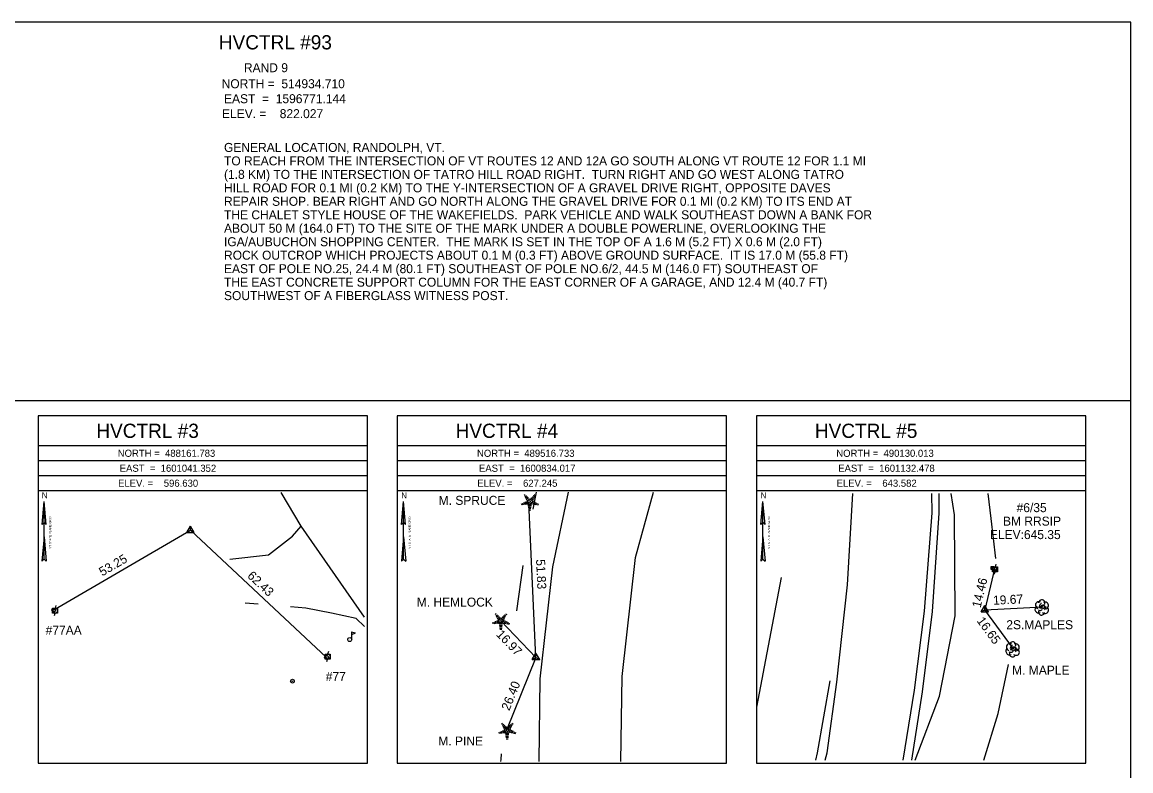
# Model space of a CAD drawing. Extents: x 1598730 to 1599370, y 501440 to 502728.
# Drawn here: x 1598999.2 to 1599369.5, y 502477.7 to 502727.8 of the extents above; entities that cross this region are included whole.
import ezdxf

# ---------------------------------------------------------------- set-up
doc = ezdxf.new("R2010")
doc.units = 0
for name, color, linetype in [('CBP', 7, 'Continuous'), ('CPBM', 7, 'Continuous'), ('CPSM', 7, 'Continuous'), ('Default', 7, 'Continuous'), ('L_C', 7, 'Continuous'), ('LARO', 7, 'Continuous'), ('LAWA', 7, 'Continuous'), ('LMB', 7, 'Continuous'), ('LTC', 7, 'Continuous'), ('LTD', 7, 'Continuous'), ('NBL1', 7, 'Continuous'), ('NBL2', 7, 'Continuous'), ('NNA_P', 7, 'Continuous'), ('PET', 7, 'Continuous'), ('RDG', 7, 'Continuous'), ('RDP', 7, 'Continuous'), ('U_C', 7, 'Continuous'), ('UP', 7, 'Continuous'), ('UPGW', 7, 'Continuous')]:
    doc.layers.add(name, color=color, linetype=linetype)

msp = doc.modelspace()

# ---------------------------------------------------------------- linework, layer by layer
at = {"layer": 'CBP'}
for centre, radius in [((1599168.51, 502567.4), 0.625), ((1599168.51, 502567.4), 0.0833), ((1599324.01, 502545.19), 0.625), ((1599324.01, 502545.19), 0.0833), ((1599009.78, 502531.49), 0.625), ((1599009.78, 502531.49), 0.0833), ((1599340.12, 502532.53), 0.625), ((1599340.12, 502532.53), 0.0833), ((1599159.14, 502527.86), 0.625), ((1599159.14, 502527.86), 0.0833), ((1599330.38, 502518.48), 0.625), ((1599100.85, 502515.65), 0.625), ((1599100.85, 502515.65), 0.0833), ((1599330.38, 502518.48), 0.0833), ((1599160.99, 502491.31), 0.625), ((1599160.99, 502491.31), 0.0833)]:
    msp.add_circle(centre, radius, dxfattribs=at)
at = {"layer": 'CPBM'}
for p, q in [((1599322.94, 502545.01), (1599322.94, 502546.01)), ((1599322.94, 502546.01), (1599323.94, 502546.01)), ((1599323.94, 502545.01), (1599322.94, 502545.01)), ((1599323.44, 502545.51), (1599323.44, 502545.51)), ((1599323.44, 502545.51), (1599323.44, 502545.51)), ((1599323.94, 502546.01), (1599323.94, 502545.01))]:
    msp.add_line(p, q, dxfattribs=at)
at = {"layer": 'CPSM'}
for p, q in [((1599054.2, 502557.37), (1599055.45, 502559.53)), ((1599054.2, 502557.37), (1599055.45, 502558.09)), ((1599054.2, 502557.37), (1599056.7, 502557.37)), ((1599056.7, 502557.37), (1599055.45, 502559.53)), ((1599055.45, 502558.09), (1599055.45, 502559.53)), ((1599055.45, 502558.09), (1599055.45, 502558.09)), ((1599055.45, 502558.09), (1599056.7, 502557.37)), ((1599319.52, 502530.82), (1599320.77, 502532.99)), ((1599319.52, 502530.82), (1599320.77, 502531.55)), ((1599319.52, 502530.82), (1599322.02, 502530.82)), ((1599322.02, 502530.82), (1599320.77, 502532.99)), ((1599320.77, 502531.55), (1599320.77, 502532.99)), ((1599320.77, 502531.55), (1599320.77, 502531.55)), ((1599320.77, 502531.55), (1599322.02, 502530.82)), ((1599169.6, 502514.94), (1599170.85, 502517.1)), ((1599169.6, 502514.94), (1599170.85, 502515.66)), ((1599172.1, 502514.94), (1599170.85, 502517.1)), ((1599170.85, 502515.66), (1599170.85, 502517.1)), ((1599170.85, 502515.66), (1599170.85, 502515.66)), ((1599170.85, 502515.66), (1599172.1, 502514.94)), ((1599169.6, 502514.94), (1599172.1, 502514.94))]:
    msp.add_line(p, q, dxfattribs=at)
at = {"layer": 'Default'}
for p, q in [((1599170.85, 502515.66), (1599168.51, 502567.4)), ((1599009.78, 502531.49), (1599055.45, 502558.09)), ((1599055.45, 502558.09), (1599100.85, 502515.65)), ((1599324.01, 502545.19), (1599320.77, 502531.55)), ((1599320.77, 502531.55), (1599340.12, 502532.53)), ((1599330.38, 502518.48), (1599320.77, 502531.55)), ((1599159.14, 502527.86), (1599170.85, 502515.66)), ((1599170.85, 502515.66), (1599160.99, 502491.31))]:
    msp.add_line(p, q, dxfattribs=at)
at = {"layer": 'LARO'}
msp.add_lwpolyline([(1599264.34, 502481.28), (1599264.89, 502483.74), (1599269.13, 502507.78)], dxfattribs=at)
at = {"layer": 'LAWA'}
for points in [[(1599169.95, 502565.19), (1599170.97, 502570.85)], [(1599324.41, 502548.64), (1599322.86, 502561.99), (1599321.92, 502570.34)], [(1599164.4, 502531.22), (1599166.57, 502546.36)], [(1599244.67, 502499.06), (1599252.84, 502542.31)], [(1599320.42, 502481.28), (1599325.28, 502496.88), (1599328.66, 502513.24)], [(1599159.16, 502480.84), (1599159.2, 502481.48), (1599159.34, 502483.44)]]:
    msp.add_lwpolyline(points, dxfattribs=at)
at = {"layer": 'LMB'}
for p, q in [((1599109.28, 502524.2), (1599110.57, 502523.82)), ((1599109.29, 502521.61), (1599109.29, 502524.21)), ((1599109.29, 502523.3), (1599110.57, 502523.81)), ((1599108.63, 502521.6), (1599108.63, 502521.6))]:
    msp.add_line(p, q, dxfattribs=at)
msp.add_circle((1599108.63, 502521.6), 0.656, dxfattribs=at)
at = {"layer": 'LTC'}
for p, q in [((1599165.93, 502567.06), (1599166.08, 502566.59)), ((1599166.38, 502567.28), (1599166.59, 502566.63)), ((1599166.84, 502567.49), (1599167.11, 502566.66)), ((1599166.89, 502569.78), (1599167.25, 502570.04)), ((1599167.1, 502569.32), (1599167.63, 502569.7)), ((1599167.29, 502567.71), (1599167.62, 502566.69)), ((1599167.31, 502568.85), (1599168.02, 502569.36)), ((1599167.52, 502568.38), (1599168.4, 502569.02)), ((1599167.75, 502567.93), (1599168.76, 502568.66)), ((1599167.75, 502567.93), (1599168.13, 502566.74)), ((1599168.76, 502568.66), (1599169.76, 502567.94)), ((1599169.18, 502568.98), (1599169.99, 502568.39)), ((1599169.76, 502567.94), (1599169.36, 502566.74)), ((1599169.55, 502569.33), (1599170.23, 502568.83)), ((1599170.19, 502567.67), (1599169.86, 502566.63)), ((1599169.92, 502569.67), (1599170.47, 502569.27)), ((1599170.29, 502570.02), (1599170.71, 502569.72)), ((1599170.64, 502567.42), (1599170.35, 502566.53)), ((1599171.08, 502567.17), (1599170.85, 502566.44)), ((1599169.36, 502566.74), (1599168.13, 502566.74)), ((1599169.33, 502566.24), (1599168.18, 502566.24)), ((1599169.24, 502565.74), (1599168.25, 502565.74)), ((1599169.16, 502565.24), (1599168.33, 502565.24)), ((1599169.07, 502564.74), (1599168.4, 502564.74)), ((1599171.53, 502566.92), (1599171.34, 502566.34)), ((1599157.25, 502530), (1599157.6, 502530.25)), ((1599160.64, 502530.24), (1599161.06, 502529.93)), ((1599156.28, 502527.27), (1599156.43, 502526.81)), ((1599156.73, 502527.49), (1599156.95, 502526.84)), ((1599157.19, 502527.71), (1599157.46, 502526.87)), ((1599157.46, 502529.53), (1599157.98, 502529.91)), ((1599157.64, 502527.92), (1599157.98, 502526.91)), ((1599157.67, 502529.06), (1599158.37, 502529.58)), ((1599157.87, 502528.6), (1599158.75, 502529.24)), ((1599158.1, 502528.14), (1599159.11, 502528.88)), ((1599158.1, 502528.14), (1599158.49, 502526.95)), ((1599159.72, 502526.95), (1599158.49, 502526.95)), ((1599159.68, 502526.45), (1599158.53, 502526.45)), ((1599159.11, 502528.88), (1599160.11, 502528.15)), ((1599159.53, 502529.19), (1599160.34, 502528.6)), ((1599160.11, 502528.15), (1599159.72, 502526.95)), ((1599159.9, 502529.54), (1599160.58, 502529.05)), ((1599160.55, 502527.88), (1599160.21, 502526.84)), ((1599160.27, 502529.89), (1599160.82, 502529.49)), ((1599160.99, 502527.63), (1599160.7, 502526.75)), ((1599161.43, 502527.38), (1599161.2, 502526.65)), ((1599161.88, 502527.13), (1599161.69, 502526.56)), ((1599159.59, 502525.95), (1599158.61, 502525.95)), ((1599159.51, 502525.45), (1599158.68, 502525.45)), ((1599159.43, 502524.95), (1599158.75, 502524.95)), ((1599159.36, 502493.43), (1599159.72, 502493.69)), ((1599159.57, 502492.96), (1599160.1, 502493.35)), ((1599159.78, 502492.5), (1599160.49, 502493.01)), ((1599162.39, 502493.32), (1599162.94, 502492.92)), ((1599162.76, 502493.67), (1599163.18, 502493.37)), ((1599158.4, 502490.71), (1599158.55, 502490.24)), ((1599158.85, 502490.93), (1599159.06, 502490.27)), ((1599159.31, 502491.14), (1599159.58, 502490.31)), ((1599159.76, 502491.36), (1599160.09, 502490.34)), ((1599159.99, 502492.03), (1599160.87, 502492.67)), ((1599160.22, 502491.58), (1599161.23, 502492.31)), ((1599160.22, 502491.58), (1599160.6, 502490.38)), ((1599161.83, 502490.38), (1599160.6, 502490.38)), ((1599161.8, 502489.88), (1599160.65, 502489.88)), ((1599161.71, 502489.38), (1599160.72, 502489.38)), ((1599161.23, 502492.31), (1599162.22, 502491.59)), ((1599161.65, 502492.63), (1599162.46, 502492.04)), ((1599162.22, 502491.59), (1599161.83, 502490.38)), ((1599162.02, 502492.97), (1599162.7, 502492.48)), ((1599162.66, 502491.32), (1599162.32, 502490.28)), ((1599163.11, 502491.07), (1599162.82, 502490.18)), ((1599163.55, 502490.82), (1599163.31, 502490.09)), ((1599164, 502490.57), (1599163.81, 502489.99)), ((1599161.63, 502488.88), (1599160.8, 502488.88)), ((1599161.54, 502488.38), (1599160.87, 502488.38))]:
    msp.add_line(p, q, dxfattribs=at)
at = {"layer": 'LTD'}
for p, q in [((1599339.75, 502532.36), (1599339.75, 502532.36)), ((1599339.75, 502532.36), (1599339.75, 502532.36)), ((1599330.03, 502518.37), (1599330.03, 502518.37)), ((1599330.03, 502518.37), (1599330.03, 502518.37))]:
    msp.add_line(p, q, dxfattribs=at)
for centre in [(1599339.8, 502533.79), (1599330.08, 502519.81)]:
    msp.add_arc(centre, 1.05, 335.5272, 180.9563, dxfattribs=at)
for centre, major_axis, ratio, start_param, end_param in [((1599338.96, 502533.03), (1.21, -0.51), 0.895232, 1.570796, 4.712389), ((1599340.79, 502532.94), (-1.14, -0.48), 0.949671, 1.570796, 4.712389), ((1599338.67, 502531.65), (0.58, -1.04), 0.959034, 3.141593, 6.283185), ((1599339.75, 502530.86), (0.26, 1.06), 0.942809, 1.570796, 4.712389), ((1599339.29, 502531.61), (-0.625, -0.083), 0.423636, 0, 3.141593), ((1599339.54, 502532.82), (-0.208, -0.792), 0.645439, 3.141593, 6.283185), ((1599340.25, 502532.19), (-0.5, 0.667), 0.989748, 3.141593, 6.283185), ((1599340.75, 502531.53), (-1.09, 0.79), 0.841452, 1.570796, 4.712389), ((1599329.24, 502519.04), (1.21, -0.51), 0.895232, 1.570796, 4.712389), ((1599329.82, 502518.83), (-0.208, -0.792), 0.645439, 3.141593, 6.283185), ((1599330.53, 502518.21), (-0.5, 0.667), 0.989748, 3.141593, 6.283185), ((1599331.07, 502518.96), (-1.14, -0.48), 0.949671, 1.570796, 4.712389), ((1599328.95, 502517.67), (0.58, -1.04), 0.959034, 3.141593, 6.283185), ((1599330.03, 502516.87), (0.26, 1.06), 0.942809, 1.570796, 4.712389), ((1599329.57, 502517.62), (-0.625, -0.083), 0.423636, 0, 3.141593), ((1599331.03, 502517.54), (-1.09, 0.79), 0.841452, 1.570796, 4.712389)]:
    msp.add_ellipse(centre, major_axis=major_axis, ratio=ratio, start_param=start_param, end_param=end_param, dxfattribs=at)
at = {"layer": 'NBL1'}
msp.add_lwpolyline([(1598729.53, 502307.83), (1599369.53, 502307.83), (1599369.53, 502727.83), (1598729.53, 502727.83)], close=True, dxfattribs=at)
at = {"layer": 'NBL2'}
for p, q in [((1598729.53, 502601.5), (1599369.53, 502601.5)), ((1599114.53, 502586.33), (1599004.53, 502586.33)), ((1599234.53, 502586.33), (1599124.53, 502586.33)), ((1599354.53, 502586.33), (1599244.53, 502586.33)), ((1599114.53, 502581.33), (1599004.53, 502581.33)), ((1599234.53, 502581.33), (1599124.53, 502581.33)), ((1599354.53, 502581.33), (1599244.53, 502581.33)), ((1599114.53, 502576.33), (1599004.53, 502576.33)), ((1599234.53, 502576.33), (1599124.53, 502576.33)), ((1599354.53, 502576.33), (1599244.53, 502576.33)), ((1599114.53, 502571.33), (1599004.53, 502571.33)), ((1599234.53, 502571.33), (1599124.53, 502571.33)), ((1599354.53, 502571.33), (1599244.53, 502571.33))]:
    msp.add_line(p, q, dxfattribs=at)
for points in [[(1599004.53, 502480.33), (1599114.53, 502480.33), (1599114.53, 502596.33), (1599004.53, 502596.33)], [(1599124.53, 502480.33), (1599234.53, 502480.33), (1599234.53, 502596.33), (1599124.53, 502596.33)], [(1599244.53, 502480.33), (1599354.53, 502480.33), (1599354.53, 502596.33), (1599244.53, 502596.33)]]:
    msp.add_lwpolyline(points, close=True, dxfattribs=at)
at = {"layer": 'NNA_P'}
for p, q in [((1599005.87, 502559.98), (1599006.56, 502567.77)), ((1599006.57, 502548.4), (1599006.56, 502567.77)), ((1599007.26, 502559.98), (1599006.56, 502567.77)), ((1599125.92, 502559.98), (1599126.61, 502567.77)), ((1599126.62, 502548.4), (1599126.61, 502567.77)), ((1599127.31, 502559.98), (1599126.61, 502567.77)), ((1599245.97, 502559.98), (1599246.67, 502567.77)), ((1599246.67, 502548.4), (1599246.67, 502567.77)), ((1599247.36, 502559.98), (1599246.67, 502567.77)), ((1599005.87, 502559.98), (1599006.57, 502560.75)), ((1599007.26, 502559.98), (1599006.57, 502560.75)), ((1599125.92, 502559.98), (1599126.62, 502560.75)), ((1599127.31, 502559.98), (1599126.62, 502560.75)), ((1599245.97, 502559.98), (1599246.67, 502560.75)), ((1599247.36, 502559.98), (1599246.67, 502560.75)), ((1599006.57, 502555.92), (1599005.85, 502547.76)), ((1599006.57, 502555.92), (1599007.29, 502547.76)), ((1599126.62, 502555.92), (1599125.9, 502547.76)), ((1599126.62, 502555.92), (1599127.34, 502547.76)), ((1599246.67, 502555.92), (1599245.95, 502547.76)), ((1599246.67, 502555.92), (1599247.39, 502547.76)), ((1599006.57, 502548.4), (1599005.85, 502547.76)), ((1599006.57, 502548.4), (1599007.29, 502547.76)), ((1599126.62, 502548.4), (1599125.9, 502547.76)), ((1599126.62, 502548.4), (1599127.34, 502547.76)), ((1599246.67, 502548.4), (1599245.95, 502547.76)), ((1599246.67, 502548.4), (1599247.39, 502547.76))]:
    msp.add_line(p, q, dxfattribs=at)
at = {"layer": 'PET'}
for points in [[(1599171.96, 502480.84), (1599172.29, 502508.47), (1599176.44, 502545.93), (1599181.75, 502570.85)], [(1599199.21, 502480.84), (1599199.58, 502509.27), (1599204.09, 502549.04), (1599210.05, 502570.85)], [(1599113.62, 502529.08), (1599092.44, 502559.47), (1599085.76, 502570.73)], [(1599267.4, 502481.28), (1599268.07, 502483.71), (1599271.37, 502507.32), (1599274.87, 502539.84), (1599276.63, 502570.34)], [(1599293.49, 502481.28), (1599297.31, 502504.72), (1599300.6, 502531.12), (1599303.2, 502563.89), (1599303.07, 502570.34)]]:
    msp.add_lwpolyline(points, dxfattribs=at)
at = {"layer": 'RDG'}
msp.add_lwpolyline([(1599297.54, 502481.28), (1599305.67, 502502.67), (1599310.83, 502529.57), (1599310.67, 502563.31), (1599309.57, 502570.34)], dxfattribs=at)
at = {"layer": 'RDP'}
for points in [[(1599296.35, 502481.28), (1599299.99, 502504.16), (1599303.24, 502530.94), (1599305.51, 502563.8), (1599305.49, 502570.34)], [(1599068.6, 502548.42), (1599081.5, 502549.94), (1599089.51, 502556.16), (1599092.44, 502559.47)], [(1599078.08, 502533.4), (1599073.71, 502533.75)], [(1599113.62, 502525.98), (1599110.81, 502528.62), (1599102.58, 502530.37), (1599093.96, 502532.14), (1599088.86, 502532.54)]]:
    msp.add_lwpolyline(points, dxfattribs=at)
at = {"layer": 'UP'}
for p, q in [((1599323.34, 502544.27), (1599323.34, 502545.94)), ((1599323.34, 502545.94), (1599325, 502545.94)), ((1599324.42, 502546.77), (1599324.17, 502545.94)), ((1599324.17, 502545.1), (1599324.17, 502545.1)), ((1599325, 502545.94), (1599325, 502544.27)), ((1599325, 502544.27), (1599323.34, 502544.27)), ((1599323.92, 502543.44), (1599324.17, 502544.27)), ((1599009.41, 502530.47), (1599009.41, 502532.13)), ((1599009.41, 502532.13), (1599011.08, 502532.13)), ((1599011.08, 502530.47), (1599009.41, 502530.47)), ((1599010, 502529.63), (1599010.25, 502530.47)), ((1599010.5, 502532.97), (1599010.25, 502532.13)), ((1599010.25, 502531.3), (1599010.25, 502531.3)), ((1599011.08, 502532.13), (1599011.08, 502530.47)), ((1599100.43, 502515.09), (1599100.43, 502516.76)), ((1599100.43, 502516.76), (1599102.1, 502516.76)), ((1599101.51, 502517.59), (1599101.26, 502516.76)), ((1599101.26, 502515.93), (1599101.26, 502515.93)), ((1599102.1, 502516.76), (1599102.1, 502515.09)), ((1599102.1, 502515.09), (1599100.43, 502515.09)), ((1599101.01, 502514.26), (1599101.26, 502515.09))]:
    msp.add_line(p, q, dxfattribs=at)
for centre in [(1599324.17, 502545.1), (1599010.25, 502531.3), (1599101.26, 502515.93)]:
    msp.add_circle(centre, 0.833, dxfattribs=at)
at = {"layer": 'UPGW'}
for radius in [0.625, 0.0833]:
    msp.add_circle((1599089.49, 502507.69), radius, dxfattribs=at)

# ---------------------------------------------------------------- texts
at = {"layer": 'Default'}
for s, p in [('GENERAL LOCATION, RANDOLPH, VT.  ', (1599066.65, 502684.49)), ('TO REACH FROM THE INTERSECTION OF VT ROUTES 12 AND 12A GO SOUTH ALONG VT ROUTE 12 FOR 1.1 MI ', (1599066.65, 502679.99)), ('(1.8 KM) TO THE INTERSECTION OF TATRO HILL ROAD RIGHT.  TURN RIGHT AND GO WEST ALONG TATRO ', (1599066.65, 502675.49)), ('HILL ROAD FOR 0.1 MI (0.2 KM) TO THE Y-INTERSECTION OF A GRAVEL DRIVE RIGHT, OPPOSITE DAVES ', (1599066.65, 502670.99)), ('REPAIR SHOP. BEAR RIGHT AND GO NORTH ALONG THE GRAVEL DRIVE FOR 0.1 MI (0.2 KM) TO ITS END AT ', (1599066.65, 502666.49)), ('THE CHALET STYLE HOUSE OF THE WAKEFIELDS.  PARK VEHICLE AND WALK SOUTHEAST DOWN A BANK FOR ', (1599066.65, 502661.99)), ('ABOUT 50 M (164.0 FT) TO THE SITE OF THE MARK UNDER A DOUBLE POWERLINE, OVERLOOKING THE ', (1599066.65, 502657.49)), ('IGA/AUBUCHON SHOPPING CENTER.  THE MARK IS SET IN THE TOP OF A 1.6 M (5.2 FT) X 0.6 M (2.0 FT) ', (1599066.65, 502652.99)), ('ROCK OUTCROP WHICH PROJECTS ABOUT 0.1 M (0.3 FT) ABOVE GROUND SURFACE.  IT IS 17.0 M (55.8 FT) ', (1599066.65, 502648.49)), ('EAST OF POLE NO.25, 24.4 M (80.1 FT) SOUTHEAST OF POLE NO.6/2, 44.5 M (146.0 FT) SOUTHEAST OF ', (1599066.65, 502643.99)), ('THE EAST CONCRETE SUPPORT COLUMN FOR THE EAST CORNER OF A GARAGE, AND 12.4 M (40.7 FT) ', (1599066.65, 502639.49)), ('SOUTHWEST OF A FIBERGLASS WITNESS POST.', (1599066.65, 502634.99))]:
    msp.add_text(s, height=3, dxfattribs=at).set_placement(p)
for s, rotation, p in [('53.25', 30.218, (1599025.99, 502542.66)), ('51.83', 272.5888, (1599170.87, 502548.38)), ('62.43', 316.9288, (1599074.21, 502542.6)), ('14.46', 76.6564, (1599319.35, 502532.03)), ('19.67', 2.9111, (1599323.59, 502533.19)), ('16.65', 306.3227, (1599317.93, 502527.82)), ('16.97', 313.8225, (1599157.37, 502523.13)), ('26.40', 67.9538, (1599161.93, 502497.63))]:
    msp.add_text(s, height=3, rotation=rotation, dxfattribs=at).set_placement(p)
at = {"layer": 'L_C'}
for s, p in [('M. SPRUCE', (1599138.34, 502566.6)), ('M. HEMLOCK', (1599131.03, 502532.61)), ('2S.MAPLES', (1599327.95, 502525.06)), ('M. MAPLE', (1599329.89, 502509.87)), ('M. PINE', (1599138.22, 502486.21))]:
    msp.add_text(s, height=3, dxfattribs=at).set_placement(p)
at = {"layer": 'LTC'}
for p in [(1599168.64, 502567.68), (1599158.99, 502527.89), (1599161.11, 502491.33)]:
    msp.add_text('.', height=1.04, rotation=270, dxfattribs=at).set_placement(p)
at = {"layer": 'NBL2'}
for s, height, p in [('     HVCTRL #93    ', 4.75, (1599056.09, 502718.74)), ('        RAND 9       ', 3, (1599064.37, 502711.12)), ('NORTH =  514934.710 ', 3, (1599065.86, 502705.77)), ('EAST  =  1596771.144', 3, (1599066.65, 502700.77)), ('ELEV. =    822.027  ', 3, (1599065.97, 502695.77)), ('     HVCTRL #3     ', 4.75, (1599015.18, 502588.96)), ('     HVCTRL #4     ', 4.75, (1599135.18, 502588.96)), ('     HVCTRL #5     ', 4.75, (1599255.18, 502588.96)), ('NORTH =  488161.783 ', 2.375, (1599031.15, 502582.64)), ('NORTH =  489516.733 ', 2.375, (1599151.15, 502582.64)), ('NORTH =  490130.013 ', 2.375, (1599271.15, 502582.64)), ('EAST  =  1601041.352', 2.375, (1599031.81, 502577.64)), ('EAST  =  1600834.017', 2.375, (1599151.81, 502577.64)), ('EAST  =  1601132.478', 2.375, (1599271.81, 502577.64)), ('ELEV. =    596.630  ', 2.375, (1599031.26, 502572.64)), ('ELEV. =    627.245  ', 2.375, (1599151.26, 502572.64)), ('ELEV. =    643.582  ', 2.375, (1599271.26, 502572.64))]:
    msp.add_text(s, height=height, dxfattribs=at).set_placement(p)
at = {"layer": 'NNA_P'}
for p in [(1599005.8, 502568.78), (1599125.85, 502568.78), (1599245.9, 502568.78)]:
    msp.add_text('N', height=1.97, dxfattribs=at).set_placement(p)
for p in [(1599008.92, 502551.96), (1599128.97, 502551.96), (1599249.02, 502551.96)]:
    msp.add_text('VT STATE PLANE GRID', height=0.7, rotation=90.0204, dxfattribs=at).set_placement(p)
at = {"layer": 'U_C'}
for s, p in [('#6/35', (1599331.39, 502564.16)), ('BM RRSIP', (1599326.84, 502559.66)), ('ELEV:645.35', (1599322.46, 502555.16)), ('#77AA', (1599007.07, 502523.2)), ('#77', (1599100.65, 502507.8))]:
    msp.add_text(s, height=3, dxfattribs=at).set_placement(p)

doc.saveas('drawing.dxf')
